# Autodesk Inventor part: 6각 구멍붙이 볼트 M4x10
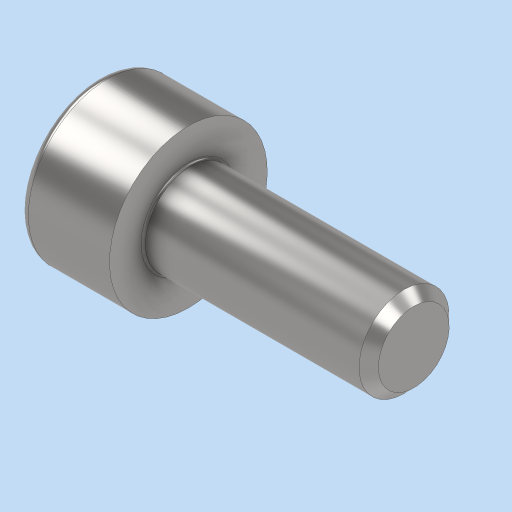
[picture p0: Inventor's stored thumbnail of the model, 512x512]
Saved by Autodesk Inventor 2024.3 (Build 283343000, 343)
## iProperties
Created: 2025-11
Part Number: 6각 구멍붙이 볼트 M4x10
Material: 강철, 연강
Description: 6각머리 태핑 나사
Document SubType Name: Modeling
Designer: PC2-02
Density: 7.85 g/cm^3
Appearance: 기본값
Author: jhkim
Sending System: Autodesk Inventor 2026
Preprocessor: ST-DEVELOPER v20.1
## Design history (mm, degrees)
node "6각 구멍붙이 볼트 M4x101"
node "솔리드1"
body "Solid1"
